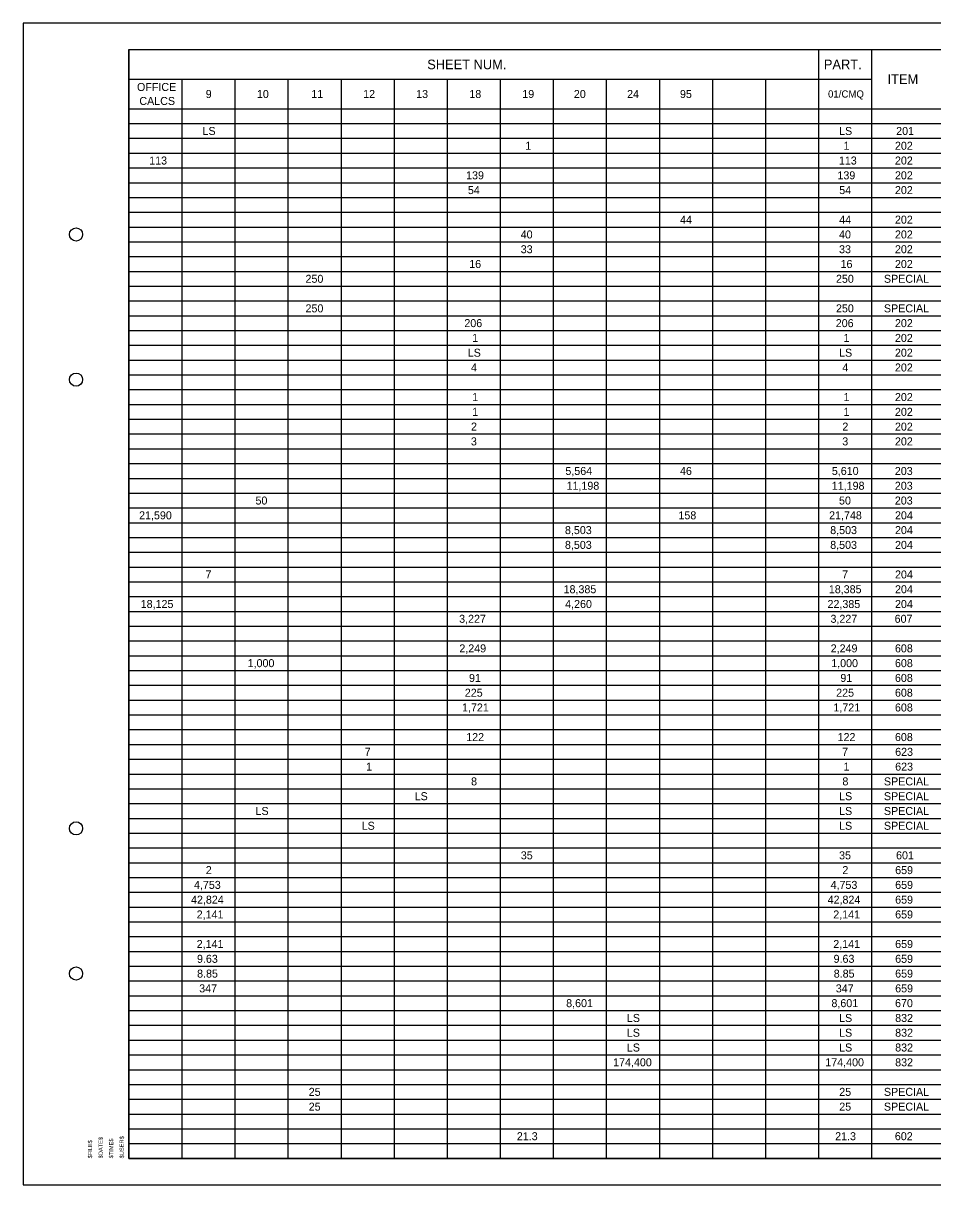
# Model space of a CAD drawing. Extents: x -16 to 102, y -13 to 9.
# Drawn here: x -16.37 to 0.85, y -12.91 to 9.09 of the extents above; entities that cross this region are included whole.
import ezdxf

# ---------------------------------------------------------------- set-up
doc = ezdxf.new("R2010")
doc.units = 0
for name, color, linetype in [('SH_Border', 7, 'Continuous'), ('SH_Cut_Line', 7, 'Continuous'), ('TX_P_1', 7, 'Continuous'), ('TX_P_Misc', 7, 'Continuous')]:
    doc.layers.add(name, color=color, linetype=linetype)

msp = doc.modelspace()

# ---------------------------------------------------------------- linework, layer by layer
at = {"layer": 'SH_Border'}
msp.add_lwpolyline([(-14.371, 8.593), (17.129, 8.593), (17.129, -12.407), (-14.371, -12.407)], close=True, dxfattribs=at)
for centre in [(-15.371, 5.093), (-15.371, 2.343), (-15.371, -6.157), (-15.371, -8.907)]:
    msp.add_circle(centre, 0.125, dxfattribs=at)
at = {"layer": 'SH_Cut_Line'}
msp.add_lwpolyline([(-16.371, -12.907), (17.629, -12.907), (17.629, 9.093), (-16.371, 9.093)], close=True, dxfattribs=at)
at = {"layer": 'TX_P_1'}
for p, q in [((-14.371, 8.593), (16.129, 8.593)), ((-14.371, 8.593), (-14.371, -12.407)), ((-1.312, 8.593), (-1.312, -12.407)), ((-0.307, 8.593), (-0.307, -12.407)), ((-14.371, 8.033), (-0.307, 8.033)), ((-13.367, 8.033), (-13.367, -12.407)), ((-12.362, 8.033), (-12.362, -12.407)), ((-11.358, 8.033), (-11.358, -12.407)), ((-10.353, 8.033), (-10.353, -12.407)), ((-9.348, 8.033), (-9.348, -12.407)), ((-8.344, 8.033), (-8.344, -12.407)), ((-7.339, 8.033), (-7.339, -12.407)), ((-6.335, 8.033), (-6.335, -12.407)), ((-5.33, 8.033), (-5.33, -12.407)), ((-4.325, 8.033), (-4.325, -12.407)), ((-3.321, 8.033), (-3.321, -12.407)), ((-2.316, 8.033), (-2.316, -12.407)), ((-14.371, 7.473), (16.129, 7.473)), ((-14.371, 7.193), (16.129, 7.193)), ((-14.371, 6.913), (16.129, 6.913)), ((-14.371, 6.633), (16.129, 6.633)), ((-14.371, 6.353), (16.129, 6.353)), ((-14.371, 6.073), (16.129, 6.073)), ((-14.371, 5.793), (16.129, 5.793)), ((-14.371, 5.513), (16.129, 5.513)), ((-14.371, 5.233), (16.129, 5.233)), ((-14.371, 4.953), (16.129, 4.953)), ((-14.371, 4.673), (16.129, 4.673)), ((-14.371, 4.393), (16.129, 4.393)), ((-14.371, 4.113), (16.129, 4.113)), ((-14.371, 3.833), (16.129, 3.833)), ((-14.371, 3.553), (16.129, 3.553)), ((-14.371, 3.273), (16.129, 3.273)), ((-14.371, 2.993), (16.129, 2.993)), ((-14.371, 2.713), (16.129, 2.713)), ((-14.371, 2.433), (16.129, 2.433)), ((-14.371, 2.153), (16.129, 2.153)), ((-14.371, 1.873), (16.129, 1.873)), ((-14.371, 1.593), (16.129, 1.593)), ((-14.371, 1.313), (16.129, 1.313)), ((-14.371, 1.033), (16.129, 1.033)), ((-14.371, 0.753), (16.129, 0.753)), ((-14.371, 0.473), (16.129, 0.473)), ((-14.371, 0.193), (16.129, 0.193)), ((-14.371, -0.087), (16.129, -0.087)), ((-14.371, -0.367), (16.129, -0.367)), ((-14.371, -0.647), (16.129, -0.647)), ((-14.371, -0.927), (16.129, -0.927)), ((-14.371, -1.207), (16.129, -1.207)), ((-14.371, -1.487), (16.129, -1.487)), ((-14.371, -1.767), (16.129, -1.767)), ((-14.371, -2.047), (16.129, -2.047)), ((-14.371, -2.327), (16.129, -2.327)), ((-14.371, -2.607), (16.129, -2.607)), ((-14.371, -2.887), (16.129, -2.887)), ((-14.371, -3.167), (16.129, -3.167)), ((-14.371, -3.447), (16.129, -3.447)), ((-14.371, -3.727), (16.129, -3.727)), ((-14.371, -4.007), (16.129, -4.007)), ((-14.371, -4.287), (16.129, -4.287)), ((-14.371, -4.567), (16.129, -4.567)), ((-14.371, -4.847), (16.129, -4.847)), ((-14.371, -5.127), (16.129, -5.127)), ((-14.371, -5.407), (16.129, -5.407)), ((-14.371, -5.687), (16.129, -5.687)), ((-14.371, -5.967), (16.129, -5.967)), ((-14.371, -6.247), (16.129, -6.247)), ((-14.371, -6.527), (16.129, -6.527)), ((-14.371, -6.807), (16.129, -6.807)), ((-14.371, -7.087), (16.129, -7.087)), ((-14.371, -7.367), (16.129, -7.367)), ((-14.371, -7.647), (16.129, -7.647)), ((-14.371, -7.927), (16.129, -7.927)), ((-14.371, -8.207), (16.129, -8.207)), ((-14.371, -8.487), (16.129, -8.487)), ((-14.371, -8.767), (16.129, -8.767)), ((-14.371, -9.047), (16.129, -9.047)), ((-14.371, -9.327), (16.129, -9.327)), ((-14.371, -9.607), (16.129, -9.607)), ((-14.371, -9.887), (16.129, -9.887)), ((-14.371, -10.167), (16.129, -10.167)), ((-14.371, -10.447), (16.129, -10.447)), ((-14.371, -10.727), (16.129, -10.727)), ((-14.371, -11.007), (16.129, -11.007)), ((-14.371, -11.287), (16.129, -11.287)), ((-14.371, -11.567), (16.129, -11.567)), ((-14.371, -11.847), (16.129, -11.847)), ((-14.371, -12.127), (16.129, -12.127)), ((-14.371, -12.407), (16.129, -12.407))]:
    msp.add_line(p, q, dxfattribs=at)

# ---------------------------------------------------------------- texts
for s, height, p in [('SHEET NUM.', 0.1818, (-8.721, 8.222)), ('PART.', 0.1818, (-1.21, 8.222)), ('OFFICE', 0.1515, (-14.217, 7.81)), ('ITEM', 0.1818, (-0.004, 7.942)), ('9', 0.152, (-12.916, 7.677)), ('10', 0.1515, (-11.946, 7.677)), ('11', 0.1515, (-10.916, 7.677)), ('12', 0.1515, (-9.934, 7.677)), ('13', 0.1515, (-8.931, 7.677)), ('18', 0.1515, (-7.923, 7.677)), ('19', 0.1515, (-6.921, 7.677)), ('20', 0.1515, (-5.944, 7.677)), ('24', 0.1515, (-4.936, 7.677)), ('95', 0.1515, (-3.935, 7.677)), ('01/CMQ', 0.1364, (-1.131, 7.685)), ('CALCS', 0.1515, (-14.172, 7.545)), ('LS', 0.1515, (-12.977, 6.977)), ('LS', 0.1515, (-0.922, 6.977)), ('201', 0.1515, (0.159, 6.977)), ('1', 0.152, (-6.865, 6.697)), ('1', 0.152, (-0.838, 6.697)), ('202', 0.1515, (0.136, 6.697)), ('113', 0.1515, (-13.986, 6.417)), ('113', 0.1515, (-0.926, 6.417)), ('202', 0.1515, (0.136, 6.417)), ('139', 0.1515, (-7.985, 6.137)), ('139', 0.1515, (-0.953, 6.137)), ('202', 0.1515, (0.136, 6.137)), ('54', 0.1515, (-7.951, 5.857)), ('54', 0.1515, (-0.919, 5.857)), ('202', 0.1515, (0.136, 5.857)), ('44', 0.1515, (-3.933, 5.297)), ('44', 0.1515, (-0.919, 5.297)), ('202', 0.1515, (0.136, 5.297)), ('40', 0.1515, (-6.951, 5.017)), ('40', 0.1515, (-0.923, 5.017)), ('202', 0.1515, (0.136, 5.017)), ('33', 0.1515, (-6.95, 4.737)), ('33', 0.1515, (-0.922, 4.737)), ('202', 0.1515, (0.136, 4.737)), ('16', 0.1515, (-7.926, 4.457)), ('16', 0.1515, (-0.894, 4.457)), ('202', 0.1515, (0.136, 4.457)), ('250', 0.1515, (-11.026, 4.177)), ('250', 0.1515, (-0.981, 4.177)), ('SPECIAL', 0.1515, (-0.073, 4.177)), ('250', 0.1515, (-11.026, 3.617)), ('250', 0.1515, (-0.981, 3.617)), ('SPECIAL', 0.1515, (-0.073, 3.617)), ('206', 0.1515, (-8.018, 3.337)), ('206', 0.1515, (-0.985, 3.337)), ('202', 0.1515, (0.136, 3.337)), ('1', 0.152, (-7.87, 3.057)), ('1', 0.152, (-0.838, 3.057)), ('202', 0.1515, (0.136, 3.057)), ('LS', 0.1515, (-7.954, 2.777)), ('LS', 0.1515, (-0.922, 2.777)), ('202', 0.1515, (0.136, 2.777)), ('4', 0.152, (-7.892, 2.497)), ('4', 0.152, (-0.86, 2.497)), ('202', 0.1515, (0.136, 2.497)), ('1', 0.152, (-7.87, 1.937)), ('1', 0.152, (-0.838, 1.937)), ('202', 0.1515, (0.136, 1.937)), ('1', 0.152, (-7.87, 1.657)), ('1', 0.152, (-0.838, 1.657)), ('202', 0.1515, (0.136, 1.657)), ('2', 0.152, (-7.892, 1.377)), ('2', 0.152, (-0.86, 1.377)), ('202', 0.1515, (0.136, 1.377)), ('3', 0.152, (-7.894, 1.097)), ('3', 0.152, (-0.862, 1.097)), ('202', 0.1515, (0.136, 1.097)), ('5,564', 0.1515, (-6.105, 0.537)), ('46', 0.1515, (-3.935, 0.537)), ('5,610', 0.1515, (-1.059, 0.537)), ('203', 0.1515, (0.134, 0.537)), ('11,198', 0.1515, (-6.083, 0.257)), ('11,198', 0.1515, (-1.06, 0.257)), ('203', 0.1515, (0.134, 0.257)), ('50', 0.1515, (-11.973, -0.023)), ('50', 0.1515, (-0.923, -0.023)), ('203', 0.1515, (0.134, -0.023)), ('21,590', 0.1515, (-14.177, -0.303)), ('158', 0.1515, (-3.964, -0.303)), ('21,748', 0.1515, (-1.111, -0.303)), ('204', 0.1515, (0.137, -0.303)), ('8,503', 0.1515, (-6.113, -0.583)), ('8,503', 0.1515, (-1.09, -0.583)), ('204', 0.1515, (0.137, -0.583)), ('8,503', 0.1515, (-6.113, -0.863)), ('8,503', 0.1515, (-1.09, -0.863)), ('204', 0.1515, (0.137, -0.863)), ('7', 0.152, (-12.92, -1.423)), ('7', 0.152, (-0.865, -1.423)), ('204', 0.1515, (0.137, -1.423)), ('18,385', 0.1515, (-6.139, -1.703)), ('18,385', 0.1515, (-1.116, -1.703)), ('204', 0.1515, (0.137, -1.703)), ('18,125', 0.1515, (-14.147, -1.983)), ('4,260', 0.1515, (-6.109, -1.983)), ('22,385', 0.1515, (-1.141, -1.983)), ('204', 0.1515, (0.137, -1.983)), ('3,227', 0.1515, (-8.117, -2.263)), ('3,227', 0.1515, (-1.085, -2.263)), ('607', 0.1515, (0.13, -2.263)), ('2,249', 0.1515, (-8.113, -2.823)), ('2,249', 0.1515, (-1.081, -2.823)), ('608', 0.1515, (0.136, -2.823)), ('1,000', 0.1515, (-12.122, -3.103)), ('1,000', 0.1515, (-1.071, -3.103)), ('608', 0.1515, (0.136, -3.103)), ('91', 0.1515, (-7.93, -3.383)), ('91', 0.1515, (-0.898, -3.383)), ('608', 0.1515, (0.136, -3.383)), ('225', 0.1515, (-8.009, -3.663)), ('225', 0.1515, (-0.977, -3.663)), ('608', 0.1515, (0.136, -3.663)), ('1,721', 0.1515, (-8.062, -3.943)), ('1,721', 0.1515, (-1.03, -3.943)), ('608', 0.1515, (0.136, -3.943)), ('122', 0.1515, (-7.983, -4.503)), ('122', 0.1515, (-0.95, -4.503)), ('608', 0.1515, (0.136, -4.503)), ('7', 0.152, (-9.906, -4.783)), ('7', 0.152, (-0.865, -4.783)), ('623', 0.1515, (0.14, -4.783)), ('1', 0.152, (-9.879, -5.063)), ('1', 0.152, (-0.838, -5.063)), ('623', 0.1515, (0.14, -5.063)), ('8', 0.152, (-7.891, -5.343)), ('8', 0.152, (-0.859, -5.343)), ('SPECIAL', 0.1515, (-0.073, -5.343)), ('LS', 0.1515, (-8.959, -5.623)), ('LS', 0.1515, (-0.922, -5.623)), ('SPECIAL', 0.1515, (-0.073, -5.623)), ('LS', 0.1515, (-11.973, -5.903)), ('LS', 0.1515, (-0.922, -5.903)), ('SPECIAL', 0.1515, (-0.073, -5.903)), ('LS', 0.1515, (-9.963, -6.183)), ('LS', 0.1515, (-0.922, -6.183)), ('SPECIAL', 0.1515, (-0.073, -6.183)), ('35', 0.1515, (-6.949, -6.743)), ('35', 0.1515, (-0.922, -6.743)), ('601', 0.1515, (0.157, -6.743)), ('2', 0.152, (-12.915, -7.023)), ('2', 0.152, (-0.86, -7.023)), ('659', 0.1515, (0.14, -7.023)), ('4,753', 0.1515, (-13.138, -7.303)), ('4,753', 0.1515, (-1.083, -7.303)), ('659', 0.1515, (0.14, -7.303)), ('42,824', 0.1515, (-13.194, -7.583)), ('42,824', 0.1515, (-1.139, -7.583)), ('659', 0.1515, (0.14, -7.583)), ('2,141', 0.1515, (-13.087, -7.863)), ('2,141', 0.1515, (-1.032, -7.863)), ('659', 0.1515, (0.14, -7.863)), ('2,141', 0.1515, (-13.087, -8.423)), ('2,141', 0.1515, (-1.032, -8.423)), ('659', 0.1515, (0.14, -8.423)), ('9.63', 0.1515, (-13.081, -8.703)), ('9.63', 0.1515, (-1.026, -8.703)), ('659', 0.1515, (0.14, -8.703)), ('8.85', 0.1515, (-13.079, -8.983)), ('8.85', 0.1515, (-1.023, -8.983)), ('659', 0.1515, (0.14, -8.983)), ('347', 0.1515, (-13.039, -9.263)), ('347', 0.1515, (-0.984, -9.263)), ('659', 0.1515, (0.14, -9.263)), ('8,601', 0.1515, (-6.09, -9.543)), ('8,601', 0.1515, (-1.067, -9.543)), ('670', 0.1515, (0.138, -9.543)), ('LS', 0.1515, (-4.94, -9.823)), ('LS', 0.1515, (-0.922, -9.823)), ('832', 0.1515, (0.14, -9.823)), ('LS', 0.1515, (-4.94, -10.103)), ('LS', 0.1515, (-0.922, -10.103)), ('832', 0.1515, (0.14, -10.103)), ('LS', 0.1515, (-4.94, -10.383)), ('LS', 0.1515, (-0.922, -10.383)), ('832', 0.1515, (0.14, -10.383)), ('174,400', 0.1515, (-5.201, -10.663)), ('174,400', 0.1515, (-1.183, -10.663)), ('832', 0.1515, (0.14, -10.663)), ('25', 0.1515, (-10.965, -11.223)), ('25', 0.1515, (-0.919, -11.223)), ('SPECIAL', 0.1515, (-0.073, -11.223)), ('25', 0.1515, (-10.965, -11.503)), ('25', 0.1515, (-0.919, -11.503)), ('SPECIAL', 0.1515, (-0.073, -11.503)), ('21.3', 0.1515, (-7.024, -12.063)), ('21.3', 0.1515, (-0.996, -12.063)), ('602', 0.1515, (0.134, -12.063))]:
    msp.add_text(s, height=height, dxfattribs=at).set_placement(p)
at = {"layer": 'TX_P_Misc'}
for s, p in [('$FILE$', (-15.067, -12.407)), ('$DATE$', (-14.867, -12.407)), ('$TIME$', (-14.667, -12.407)), ('$USER$', (-14.467, -12.407))]:
    msp.add_text(s, height=0.078, rotation=90, dxfattribs=at).set_placement(p)

doc.saveas('drawing.dxf')
